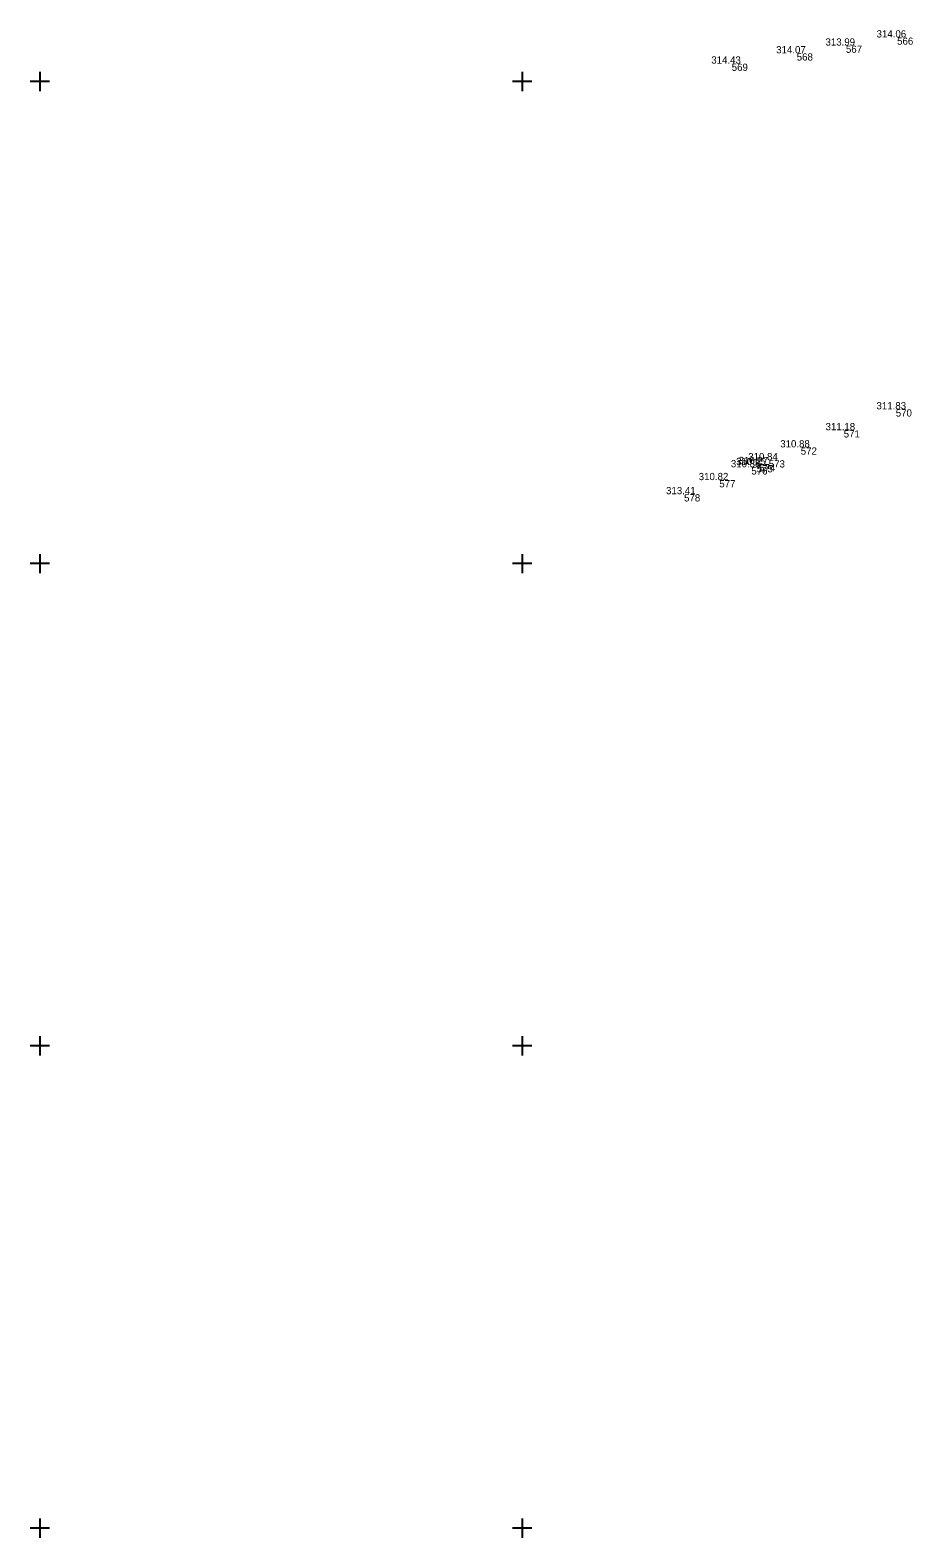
# Model space of a CAD drawing. Extents: x -718951 to -718443, y -1070201 to -1068444.
# Drawn here: x -718951 to -718859.5, y -1069951 to -1069794.7 of the extents above; entities that cross this region are included whole.
import ezdxf

# ---------------------------------------------------------------- set-up
doc = ezdxf.new("R2010")
doc.units = 0
for name, color, linetype in [('GEO_Body polohopis', 7, 'Continuous'), ('GEO_Hektarová síť', 7, 'Continuous'), ('GEO_Výšky bodů polohopis', 7, 'Continuous'), ('GEO_Čísla bodů polohopis', 7, 'Continuous')]:
    doc.layers.add(name, color=color, linetype=linetype)

msp = doc.modelspace()

# ---------------------------------------------------------------- linework, layer by layer
at = {"layer": 'GEO_Body polohopis'}
for p, q in [((-718866.42, -1069796.29), (-718866.42, -1069796.29)), ((-718861.11, -1069795.45), (-718861.11, -1069795.45)), ((-718878.26, -1069798.16), (-718878.26, -1069798.16)), ((-718871.52, -1069797.09), (-718871.52, -1069797.09)), ((-718861.25, -1069834), (-718861.25, -1069834)), ((-718866.65, -1069836.17), (-718866.65, -1069836.17)), ((-718871.1, -1069837.95), (-718871.1, -1069837.95)), ((-718876.23, -1069840.01), (-718876.23, -1069840.01)), ((-718875.67, -1069839.78), (-718875.67, -1069839.78)), ((-718875.42, -1069839.68), (-718875.42, -1069839.68)), ((-718874.42, -1069839.28), (-718874.42, -1069839.28)), ((-718879.55, -1069841.34), (-718879.55, -1069841.34)), ((-718883.2, -1069842.8), (-718883.2, -1069842.8))]:
    msp.add_line(p, q, dxfattribs=at)
at = {"layer": 'GEO_Hektarová síť'}
for points in [[(-718950, -1069799), (-718950, -1069800), (-718950, -1069801)], [(-718900, -1069799), (-718900, -1069800), (-718900, -1069801)], [(-718949, -1069800), (-718950, -1069800), (-718951, -1069800)], [(-718899, -1069800), (-718900, -1069800), (-718901, -1069800)], [(-718950, -1069849), (-718950, -1069850), (-718950, -1069851)], [(-718900, -1069849), (-718900, -1069850), (-718900, -1069851)], [(-718949, -1069850), (-718950, -1069850), (-718951, -1069850)], [(-718899, -1069850), (-718900, -1069850), (-718901, -1069850)], [(-718950, -1069899), (-718950, -1069900), (-718950, -1069901)], [(-718900, -1069899), (-718900, -1069900), (-718900, -1069901)], [(-718949, -1069900), (-718950, -1069900), (-718951, -1069900)], [(-718899, -1069900), (-718900, -1069900), (-718901, -1069900)], [(-718949, -1069950), (-718950, -1069950), (-718951, -1069950)], [(-718950, -1069949), (-718950, -1069950), (-718950, -1069951)], [(-718899, -1069950), (-718900, -1069950), (-718901, -1069950)], [(-718900, -1069949), (-718900, -1069950), (-718900, -1069951)]]:
    msp.add_lwpolyline(points, dxfattribs=at)

# ---------------------------------------------------------------- texts
at = {"layer": 'GEO_Výšky bodů polohopis'}
for s, p in [('314.06 ', (-718863.24, -1069795.45)), ('314.07 ', (-718873.65, -1069797.09)), ('313.99 ', (-718868.54, -1069796.29)), ('314.43 ', (-718880.38, -1069798.16)), ('311.83 ', (-718863.25, -1069834)), ('311.18 ', (-718868.53, -1069836.17)), ('310.88 ', (-718873.23, -1069837.95)), ('310.25 ', (-718877.8, -1069839.78)), ('310.27 ', (-718877.55, -1069839.68)), ('310.84 ', (-718876.55, -1069839.28)), ('310.82 ', (-718881.68, -1069841.34)), ('310.38 ', (-718878.35, -1069840.01)), ('313.41 ', (-718885.07, -1069842.8))]:
    msp.add_text(s, height=0.75, dxfattribs=at).set_placement(p)
at = {"layer": 'GEO_Čísla bodů polohopis'}
for s, p in [('567', (-718866.42, -1069797.04)), ('566', (-718861.11, -1069796.2)), ('569', (-718878.26, -1069798.91)), ('568', (-718871.52, -1069797.84)), ('570', (-718861.25, -1069834.75)), ('571', (-718866.65, -1069836.92)), ('572', (-718871.1, -1069838.7)), ('576', (-718876.23, -1069840.76)), ('575', (-718875.67, -1069840.53)), ('574', (-718875.42, -1069840.43)), ('573', (-718874.42, -1069840.03)), ('577', (-718879.55, -1069842.09)), ('578', (-718883.2, -1069843.55))]:
    msp.add_text(s, height=0.75, dxfattribs=at).set_placement(p)

doc.saveas('drawing.dxf')
